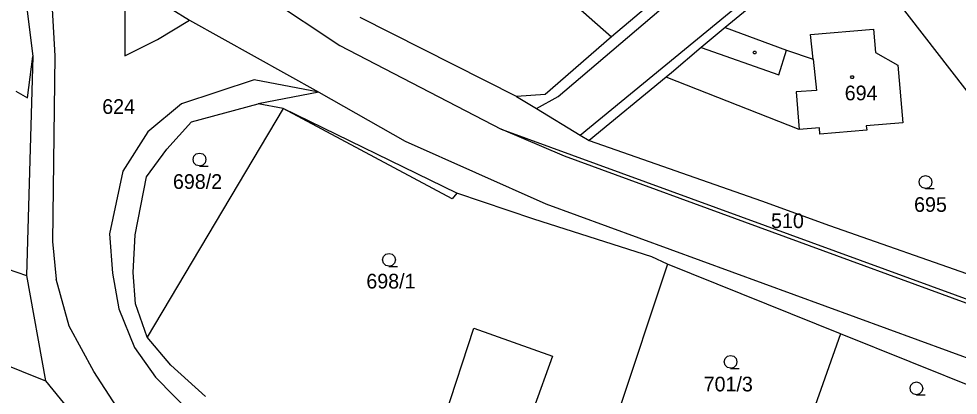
# Model space of a CAD drawing. Extents: x -621797 to -620972, y -1175539 to -1174697.
# Drawn here: x -621483.9 to -621375.1, y -1174986.3 to -1174942.7 of the extents above; entities that cross this region are included whole.
import ezdxf

# ---------------------------------------------------------------- set-up
doc = ezdxf.new("R2010")
doc.units = 0
for name, color, linetype in [('INZ mimo EON - nadz', 7, 'Continuous'), ('Rozvod plynu EON', 7, 'Continuous'), ('SDEL EON', 7, 'Continuous'), ('SDEL EON - popis', 7, 'Continuous'), ('Silnoproud EON', 7, 'Continuous'), ('Silnoproud EON - popis', 7, 'Continuous')]:
    doc.layers.add(name, color=color, linetype=linetype)

msp = doc.modelspace()

# ---------------------------------------------------------------- linework, layer by layer
at = {"layer": 'Rozvod plynu EON'}
for points in [[(-621398.59, -1174946.48), (-621398.5, -1174946.63), (-621398.59, -1174946.78), (-621398.77, -1174946.78), (-621398.86, -1174946.63), (-621398.77, -1174946.48)], [(-621387.3, -1174949.32), (-621387.21, -1174949.47), (-621387.3, -1174949.62), (-621387.48, -1174949.62), (-621387.57, -1174949.47), (-621387.48, -1174949.32)]]:
    msp.add_lwpolyline(points, close=True, dxfattribs=at)
at = {"layer": 'SDEL EON'}
for points in [[(-621462.95, -1174959.74), (-621463.33, -1174959.64), (-621463.6, -1174959.37), (-621463.7, -1174959), (-621463.6, -1174958.63), (-621463.33, -1174958.36), (-621462.96, -1174958.26), (-621462.59, -1174958.36), (-621462.32, -1174958.63), (-621462.22, -1174959.01), (-621462.32, -1174959.39), (-621462.59, -1174959.66), (-621462.97, -1174959.76), (-621461.97, -1174959.76)], [(-621378.89, -1174962.34), (-621379.27, -1174962.24), (-621379.54, -1174961.97), (-621379.64, -1174961.6), (-621379.54, -1174961.23), (-621379.27, -1174960.96), (-621378.9, -1174960.86), (-621378.53, -1174960.96), (-621378.26, -1174961.23), (-621378.16, -1174961.61), (-621378.26, -1174961.99), (-621378.53, -1174962.26), (-621378.91, -1174962.36), (-621377.91, -1174962.36)], [(-621441.01, -1174971.35), (-621441.39, -1174971.25), (-621441.66, -1174970.98), (-621441.76, -1174970.61), (-621441.66, -1174970.24), (-621441.39, -1174969.97), (-621441.02, -1174969.87), (-621440.65, -1174969.97), (-621440.38, -1174970.24), (-621440.28, -1174970.62), (-621440.38, -1174971), (-621440.65, -1174971.27), (-621441.03, -1174971.37), (-621440.03, -1174971.37)], [(-621401.46, -1174983.16), (-621401.84, -1174983.06), (-621402.11, -1174982.79), (-621402.21, -1174982.42), (-621402.11, -1174982.05), (-621401.84, -1174981.78), (-621401.47, -1174981.68), (-621401.1, -1174981.78), (-621400.83, -1174982.05), (-621400.73, -1174982.43), (-621400.83, -1174982.81), (-621401.1, -1174983.08), (-621401.48, -1174983.18), (-621400.48, -1174983.18)], [(-621379.94, -1174986.22), (-621380.32, -1174986.12), (-621380.59, -1174985.85), (-621380.69, -1174985.48), (-621380.59, -1174985.11), (-621380.32, -1174984.84), (-621379.95, -1174984.74), (-621379.58, -1174984.84), (-621379.31, -1174985.11), (-621379.21, -1174985.49), (-621379.31, -1174985.87), (-621379.58, -1174986.14), (-621379.96, -1174986.24), (-621378.96, -1174986.24)]]:
    msp.add_lwpolyline(points, dxfattribs=at)
at = {"layer": 'SDEL EON - popis'}
for p, q in [((-621421.45, -1174951.71), (-621399.66, -1174933.17)), ((-621480.32, -1174936.32), (-621479.72, -1174947)), ((-621418.87, -1174956.17), (-621394.09, -1174935.82)), ((-621471.62, -1174938.22), (-621471.6, -1174947.02)), ((-621467.83, -1174945.11), (-621464.11, -1174942.87)), ((-621471.6, -1174947.02), (-621467.83, -1174945.11)), ((-621404.87, -1174946.05), (-621395.9, -1174949.2)), ((-621395.9, -1174949.2), (-621394.99, -1174946.33)), ((-621479.72, -1174947), (-621479.99, -1174968.49)), ((-621391.91, -1174947.39), (-621391.54, -1174951.01)), ((-621456.64, -1174949.77), (-621465.06, -1174952.55)), ((-621449.16, -1174951.2), (-621456.64, -1174949.77)), ((-621449.16, -1174951.2), (-621439.13, -1174956.88)), ((-621423.93, -1174953.1), (-621421.45, -1174951.71)), ((-621391.54, -1174951.01), (-621393.89, -1174951.15)), ((-621393.89, -1174951.15), (-621393.53, -1174955.53)), ((-621465.06, -1174952.55), (-621468.96, -1174955.8)), ((-621433.69, -1174963.55), (-621453.26, -1174953.1)), ((-621468.96, -1174955.8), (-621471.84, -1174960.36)), ((-621420.71, -1174958.62), (-621428.04, -1174955.5)), ((-621439.13, -1174956.88), (-621422.85, -1174964.14)), ((-621364.76, -1174979.08), (-621420.71, -1174958.62)), ((-621471.84, -1174960.36), (-621473.37, -1174967.61)), ((-621433.15, -1174962.88), (-621433.69, -1174963.55)), ((-621422.85, -1174964.14), (-621368.03, -1174984.17)), ((-621499.01, -1174966.83), (-621483.01, -1174972.44)), ((-621473.37, -1174967.61), (-621473.03, -1174972.14)), ((-621479.99, -1174968.49), (-621479.57, -1174972.86)), ((-621473.03, -1174972.14), (-621472.3, -1174976.27)), ((-621478.04, -1174978.29), (-621479.57, -1174972.86)), ((-621472.3, -1174976.27), (-621470.48, -1174980.76)), ((-621475.19, -1174983.54), (-621478.04, -1174978.29)), ((-621470.48, -1174980.76), (-621468.04, -1174984.21)), ((-621472.58, -1174987.57), (-621475.19, -1174983.54)), ((-621468.04, -1174984.21), (-621463.78, -1174988.57))]:
    msp.add_line(p, q, dxfattribs=at)
at = {"layer": 'Silnoproud EON'}
for p, q in [((-621429.73, -1174931.98), (-621415.27, -1174944.81)), ((-621483.68, -1174935.67), (-621482.27, -1174947.07)), ((-621393.6, -1174936.71), (-621402.08, -1174943.74)), ((-621406.03, -1174936.98), (-621415.27, -1174944.81)), ((-621471.62, -1174938.22), (-621464.11, -1174942.87)), ((-621457.21, -1174938.83), (-621446.7, -1174945.8)), ((-621364.82, -1174963.05), (-621384.13, -1174938.12)), ((-621464.11, -1174942.87), (-621449.16, -1174951.2)), ((-621426.26, -1174951.7), (-621444.34, -1174942.56)), ((-621402.08, -1174943.74), (-621404.87, -1174946.05)), ((-621402.08, -1174943.74), (-621394.99, -1174946.33)), ((-621392.2, -1174944.52), (-621384.92, -1174943.9)), ((-621384.92, -1174943.9), (-621384.69, -1174946.63)), ((-621415.27, -1174944.81), (-621422.92, -1174951.46)), ((-621391.91, -1174947.39), (-621392.2, -1174944.52)), ((-621446.7, -1174945.8), (-621428.04, -1174955.5)), ((-621404.87, -1174946.05), (-621408.33, -1174948.95)), ((-621394.99, -1174946.33), (-621391.91, -1174947.39)), ((-621482.27, -1174947.07), (-621483.01, -1174972.44)), ((-621482.87, -1174951.87), (-621482.27, -1174947.07)), ((-621384.69, -1174946.63), (-621382.12, -1174948.07)), ((-621382.12, -1174948.07), (-621381.51, -1174954.74)), ((-621408.94, -1174949.46), (-621417.85, -1174956.8)), ((-621408.33, -1174948.95), (-621408.94, -1174949.46)), ((-621393.53, -1174955.53), (-621408.94, -1174949.46)), ((-621484.23, -1174951.09), (-621482.87, -1174951.87)), ((-621449.16, -1174951.2), (-621456.15, -1174952.55)), ((-621422.92, -1174951.46), (-621426.26, -1174951.7)), ((-621426.26, -1174951.7), (-621423.93, -1174953.1)), ((-621453.26, -1174953.1), (-621469.01, -1174979.57)), ((-621463.89, -1174954.65), (-621456.15, -1174952.55)), ((-621453.26, -1174953.1), (-621456.15, -1174952.55)), ((-621433.15, -1174962.88), (-621453.26, -1174953.1)), ((-621423.93, -1174953.1), (-621418.87, -1174956.17)), ((-621466.74, -1174957.79), (-621463.89, -1174954.65)), ((-621381.51, -1174954.74), (-621385.76, -1174955.1)), ((-621385.76, -1174955.1), (-621385.71, -1174955.59)), ((-621428.04, -1174955.5), (-621370.54, -1174976.47)), ((-621418.87, -1174956.17), (-621417.85, -1174956.8)), ((-621391.18, -1174955.33), (-621393.53, -1174955.53)), ((-621391.12, -1174956.05), (-621391.18, -1174955.33)), ((-621385.71, -1174955.59), (-621391.12, -1174956.05)), ((-621417.85, -1174956.8), (-621397.89, -1174963.8)), ((-621469.09, -1174961.01), (-621466.74, -1174957.79)), ((-621470.41, -1174967.72), (-621469.09, -1174961.01)), ((-621424.26, -1174965.92), (-621433.15, -1174962.88)), ((-621397.89, -1174963.8), (-621390, -1174966.65)), ((-621410.58, -1174970.28), (-621424.26, -1174965.92)), ((-621390, -1174966.65), (-621369.52, -1174973.82)), ((-621470.66, -1174972.07), (-621470.41, -1174967.72)), ((-621408.78, -1174971.11), (-621410.58, -1174970.28)), ((-621408.78, -1174971.11), (-621414.62, -1174988.62)), ((-621388.75, -1174979.17), (-621408.78, -1174971.11)), ((-621483.01, -1174972.44), (-621480.81, -1174984.62)), ((-621470.38, -1174975.71), (-621470.66, -1174972.07)), ((-621469.01, -1174979.57), (-621470.38, -1174975.71)), ((-621494.53, -1174979.08), (-621480.81, -1174984.62)), ((-621437.78, -1174998.47), (-621431.19, -1174978.52)), ((-621431.19, -1174978.52), (-621422.1, -1174981.75)), ((-621388.75, -1174979.17), (-621394.87, -1174996.57)), ((-621364.26, -1174989.02), (-621388.75, -1174979.17)), ((-621466.27, -1174982.79), (-621469.01, -1174979.57)), ((-621422.1, -1174981.75), (-621424.29, -1174987.85)), ((-621462.25, -1174986.43), (-621466.27, -1174982.79)), ((-621480.81, -1174984.62), (-621469.86, -1174997.98))]:
    msp.add_line(p, q, dxfattribs=at)

# ---------------------------------------------------------------- texts
at = {"layer": 'INZ mimo EON - nadz'}
for s, p in [('624', (-621474.223, -1174953.72)), ('510', (-621396.783, -1174966.94))]:
    msp.add_text(s, height=1.7, dxfattribs=at).set_placement(p)
at = {"layer": 'Silnoproud EON - popis'}
for s, p in [('694', (-621388.253, -1174952.15)), ('698/2', (-621466.033, -1174962.4)), ('695', (-621380.223, -1174965.06)), ('698/1', (-621443.643, -1174973.93)), ('701/3', (-621404.583, -1174985.84))]:
    msp.add_text(s, height=1.7, dxfattribs=at).set_placement(p)

doc.saveas('drawing.dxf')
